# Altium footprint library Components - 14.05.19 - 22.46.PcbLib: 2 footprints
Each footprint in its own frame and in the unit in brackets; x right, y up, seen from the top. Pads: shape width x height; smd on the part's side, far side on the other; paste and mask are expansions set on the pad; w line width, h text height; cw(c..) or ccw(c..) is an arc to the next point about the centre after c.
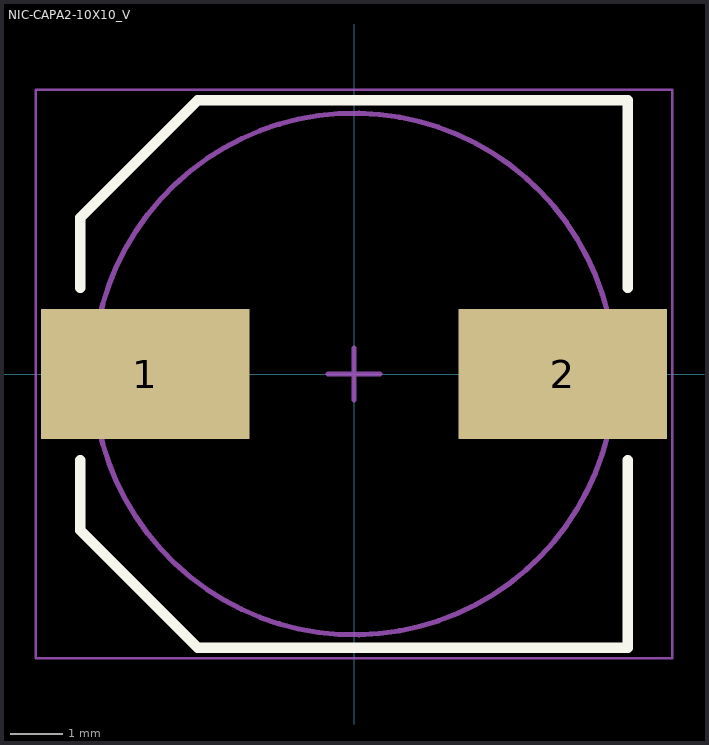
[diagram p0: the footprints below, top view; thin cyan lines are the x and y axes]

## NIC-CAPA2-10X10_V [mm] "Aluminum Electrolytic Capacitor, Diameter 10mm, Height 10.8mm, Pitch 8mm"
height 10.8
pads (2):
  rect 4x2.5 smd: 1(-4,0) 2(4,0)
Top Overlay:
  lines w0.2: -5.25,-1.65 -5.25,-3 -3,-5.25 5.25,-5.25 5.25,-1.65 ; -5.25,1.65 -5.25,3 -3,5.25 5.25,5.25 5.25,1.65
Mechanical 13:
  circle w0.1: c0,0 r5
Mechanical 15:
  lines w0.05: -6.1,-5.45 6.1,-5.45 6.1,5.45 -6.1,5.45 -6.1,-5.45
  lines w0.1: -0.5,0 0.5,0 ; 0,-0.5 0,0.5
3D body: height 10.8, standoff 0, extent -4.96,-4.99 5,4.99

## PCBComponent_1 [mm]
